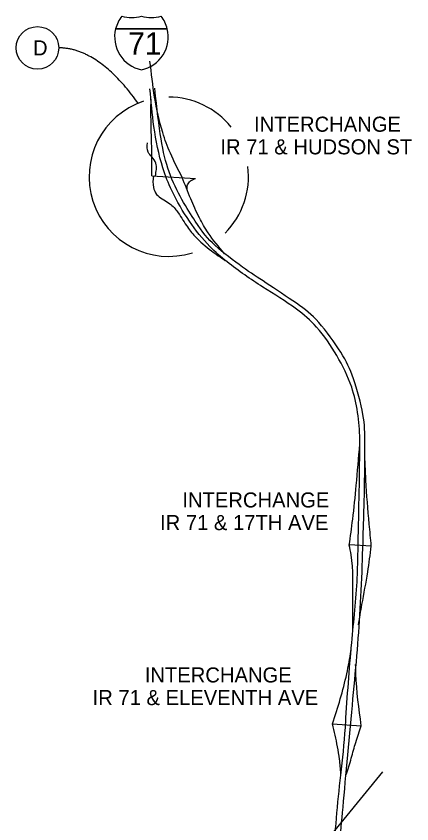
# Model space of a CAD drawing. Extents: x -13 to 322, y -402 to 112.
# Drawn here: x 1.13 to 4.13, y 106.3 to 112.43 of the extents above; entities that cross this region are included whole.
import ezdxf

# ---------------------------------------------------------------- set-up
doc = ezdxf.new("R2010")
doc.units = 0
for name, color, linetype in [('GM_X_Interstate_Shield', 7, 'Continuous'), ('SC_Scratch1', 7, 'Continuous'), ('SH_Data', 7, 'Continuous'), ('SH_Text', 7, 'Continuous')]:
    doc.layers.add(name, color=color, linetype=linetype)

msp = doc.modelspace()

# ---------------------------------------------------------------- linework, layer by layer
at = {"layer": 'GM_X_Interstate_Shield'}
for p, q in [((1.8834, 112.3304), (2.2746, 112.3304)), ((2.2746, 112.3304), (1.8834, 112.3304)), ((2.2746, 112.3304), (1.8834, 112.3304))]:
    msp.add_line(p, q, dxfattribs=at)
for centre, start, end in [((2.1299, 112.268), 141.66896, 165.80665), ((2.0047, 112.6688), 253.00908, 286.99093), ((2.1533, 112.6688), 253.00908, 286.99093), ((2.0282, 112.268), 14.19335, 38.33104), ((2.1299, 112.268), 165.80665, 258.46304), ((2.0282, 112.268), 281.53696, 14.19335)]:
    msp.add_arc(centre, 0.2542, start, end, dxfattribs=at)
at = {"layer": 'SC_Scratch1'}
msp.add_line((3.9038, 106.6966), (3.3082, 105.9659), dxfattribs=at)
at = {"layer": 'SH_Data'}
for p, q in [((2.1572, 111.216), (2.4876, 111.1959)), ((3.8196, 108.4086), (3.6534, 108.4181)), ((3.5264, 107.0604), (3.7433, 107.0457))]:
    msp.add_line(p, q, dxfattribs=at)
msp.add_circle((1.2913, 112.1852), 0.1612, dxfattribs=at)
for start, end in [(108.43701, 287.28571), (38.5563, 89.99814), (314.9928, 7.36719)]:
    msp.add_arc((2.2858, 111.2082), 0.6036, start, end, dxfattribs=at)
for points, degree in [([(2.0537, 111.7654), (1.7531, 112.1852), (1.4524, 112.1852)], 2), ([(3.746, 104.6689), (3.7, 104.9919), (3.6496, 105.3161), (3.5602, 105.9597), (3.5923, 106.2792), (3.6806, 107.2532), (3.7425, 107.9064), (3.7649, 108.7199), (3.7698, 108.883), (3.7702, 109.2113), (3.7707, 109.3812), (3.6831, 109.7044), (3.6074, 109.8565), (3.4132, 110.1323), (3.2743, 110.2359), (3.0026, 110.4169), (2.862, 110.5067), (2.6127, 110.6968), (2.512, 110.8246), (2.2567, 111.2315), (2.2141, 111.5548), (2.1799, 111.8793)], 3)]:
    msp.add_open_spline(points, degree=degree, dxfattribs=at)
for points in [[(2.3876, 111.202), (2.2979, 111.3875), (2.2399, 111.5426), (2.1433, 112.0852)], [(3.7092, 104.6637), (3.5843, 105.5418), (3.5502, 105.8224), (3.5419, 106.018), (3.5884, 106.6724), (3.6232, 107.0317), (3.6255, 107.0682), (3.6713, 107.6752), (3.713, 108.1683), (3.7189, 108.3717), (3.7325, 109.1742), (3.7325, 109.2177), (3.7156, 109.4217), (3.6709, 109.6129), (3.5578, 109.8519), (3.4048, 110.0687), (3.2534, 110.2041), (2.9985, 110.3714), (2.7278, 110.5625), (2.5969, 110.6787), (2.4431, 110.8702), (2.3082, 111.1041), (2.2413, 111.2745), (2.1732, 111.5886), (2.143, 111.8754)], [(2.1572, 111.216), (2.1572, 111.418), (2.1521, 111.5882), (2.1514, 111.796)], [(2.1842, 111.2143), (2.1876, 111.3109), (2.1578, 111.3579), (2.1303, 111.3951), (2.1235, 111.4643)], [(2.1697, 111.2152), (2.1697, 111.1267), (2.194, 111.0748), (2.2836, 111.0106), (2.3472, 110.9487), (2.4191, 110.8381), (2.4849, 110.7563), (2.6093, 110.6468), (2.7137, 110.5731)], [(2.7081, 110.625), (2.5837, 110.7838), (2.5174, 110.8972), (2.4521, 111.0415), (2.3876, 111.202)], [(2.4256, 111.1075), (2.4256, 111.1387), (2.4435, 111.1701), (2.4729, 111.1899), (2.4876, 111.1959)], [(3.653, 108.4154), (3.6788, 108.6109), (3.7055, 108.8682), (3.7326, 109.1815)], [(3.8196, 108.4086), (3.8042, 108.5749), (3.7783, 108.9074), (3.77, 109.1246)], [(3.68, 107.7786), (3.68, 107.9914), (3.6664, 108.3421), (3.653, 108.4154)], [(3.7233, 107.811), (3.7489, 107.9647), (3.793, 108.2122), (3.8196, 108.4086)], [(3.5264, 107.0604), (3.6338, 107.4395), (3.6668, 107.6164)], [(3.7433, 107.0457), (3.703, 107.4388), (3.701, 107.5101)], [(3.5893, 106.6827), (3.5791, 106.7927), (3.564, 106.8873), (3.5264, 107.0604)], [(3.6279, 106.6717), (3.6683, 106.8008), (3.7016, 106.9196), (3.7433, 107.0457)]]:
    msp.add_spline(points, degree=3, dxfattribs=at)

# ---------------------------------------------------------------- texts
at = {"layer": 'GM_X_Interstate_Shield'}
msp.add_text('71', height=0.16947, dxfattribs=at).set_placement((1.9781, 112.1333))
at = {"layer": 'SH_Data'}
msp.add_text('D', height=0.1144, dxfattribs=at).set_placement((1.2575, 112.128))
at = {"layer": 'SH_Text'}
for s, p in [('INTERCHANGE', (2.9312, 111.5494)), ('IR 71 & HUDSON ST', (2.6768, 111.3778)), ('INTERCHANGE', (2.3886, 108.7007)), ('IR 71 & 17TH AVE', (2.2198, 108.5291)), ('INTERCHANGE', (2.1039, 107.374)), ('IR 71 & ELEVENTH AVE', (1.7091, 107.2024))]:
    msp.add_text(s, height=0.114366, dxfattribs=at).set_placement(p)

doc.saveas('drawing.dxf')
